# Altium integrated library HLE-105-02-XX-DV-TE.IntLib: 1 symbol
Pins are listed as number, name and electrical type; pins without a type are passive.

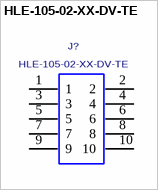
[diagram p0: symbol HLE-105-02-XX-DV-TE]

## HLE-105-02-XX-DV-TE
designator J?
.100 C.L. SINGLE BEAM SOCKET STRIP, TOP ENTRY.; MANUFACTURER: SAMTEC
footprint HLE-105-02-XX-DV-TE
pins: 1, 2, 3, 4, 5, 6, 7, 8, 9, 10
